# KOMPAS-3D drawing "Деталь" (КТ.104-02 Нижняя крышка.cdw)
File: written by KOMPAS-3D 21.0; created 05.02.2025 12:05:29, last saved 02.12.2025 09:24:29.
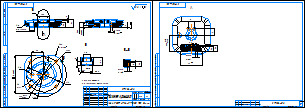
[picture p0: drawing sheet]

Sheets 1-2: A3, landscape

Document properties: Автор: User; Знак неуказанной шероховатости: 4; Параметр неуказанной шероховатости: 3,2; Масса: 1.126053; Форматы листов документа: 2xA3; Полное имя файла: КТ.104-02 Нижняя крышка.m3d

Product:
- Part/product: Деталь
    Масса: 1.126053

Title block, sheet 1: Наименование: Нижняя крышка; designation: КТ.104-02; Материал: АМг6 ГОСТ 4784-97; Масса: 1,13; sheet number: 1; Количество листов документа: 2; organisation: ООО ТПК Пегас; Форматы листов документа: A3; stored path: D:\Marat\work\eholot\KazanTarget\Новые проекты\КТ Pro\детали\Нижняя крышка\Нижняя крышка.cdw; Разработал: Гайсин
Title block, sheet 2: sheet number: 2

Views: Вид 1, Местный разрез 1, Слева, Проекционный вид 2, Вид по стрелке А, Разрез Б-Б, Проекционный вид 7, Местный разрез 2, Местный разрез 3, Выносной элемент 9, Разрез В-В, Выносной элемент Б, Выносной элемент
Referenced files in C:\Users\User\Desktop\Pelorus PRO доработки\Крышка нижняя\: п1.m3d, КТ.104-02 Нижняя крышка.m3d
Referenced files in D:\Marat\work\eholot\KazanTarget\Новые проекты\КТ Pro\детали\Нижняя крышка\: Нижняя крышка.m3d
Dimensions and other numbers on the sheet: 15; 32; 20; 12; 2; 98; 105±0,1; 126; 23; 8 мест; 14; 73; 60; 4 рад; 61; 16; 18; 27; 44,5; 13; 6-7H; 2 отв; 10; -7Н; 6; 4 отв; 13,2; 5,5±0,1; 7; 8; 30; 1,6; 1; 4; 3,2; 1:1; 1,13

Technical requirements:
  H14, h14, ±IT14/2.
  Неуказанные фаски 0.5х45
